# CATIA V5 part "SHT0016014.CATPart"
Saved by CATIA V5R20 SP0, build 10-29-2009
Part number: SHT0016014
Source: Unknown
Bounding box of the stored display mesh (mm): x -544.085 to 25.758, y -866.5 to -591.5, z 0.9 to 106.4
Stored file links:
  C:\Users\hp\Desktop\SHT0016014-宽车主驾驶底部支架焊接总成\SHT0016014.CATPart
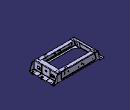
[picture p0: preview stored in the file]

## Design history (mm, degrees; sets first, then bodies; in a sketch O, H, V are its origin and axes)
Body1 "Q37108-焊接方螺母" (main body)
  Solid1: solid without history
Body2 "Q37108-焊接方螺母"
  Solid2: solid without history
Body3 "Q37108-焊接方螺母"
  Solid3: solid without history
Body4 "Q37108-焊接方螺母"
  Solid4: solid without history
Body5 "Q37108-焊接方螺母"
  Solid5: solid without history
Body6 "Q37108-焊接方螺母"
  Solid6: solid without history
Body7 "SHT0016148-宽车主驾驶左侧钣金"
  Solid7: solid without history
Body8 "SHT0016146-宽车主驾驶后侧钣金"
  Solid8: solid without history
Body9 "SHT0016145-宽车主驾驶前侧钣金"
  Solid9: solid without history
Body10 "Q37110-焊接方螺母"
  Solid10: solid without history
Body11 "Q37110-焊接方螺母"
  Solid11: solid without history
Body12 "Q37106-焊接方螺母"
  Solid12: solid without history
Body13 "Q37106-焊接方螺母"
  Solid13: solid without history
Body14 "Q37106-焊接方螺母"
  Solid14: solid without history
Body15 "Q37106-焊接方螺母"
  Solid15: solid without history
Body16 "SHT0016151-支撑轴套"
  Solid16: solid without history
Body17 "SHT0016151-支撑轴套"
  Solid17: solid without history
Body18 "SHT0016151-支撑轴套"
  Solid18: solid without history
Body19 "SHT0016149-宽车主驾驶右侧钣金"
  Solid19: solid without history
Body20 "Q37110-焊接方螺母--M10"
  Sketch1 on face of Solid7, origin (0, -861.5005, 0), H (-1, 0, 0), V (0, 0, 1)
    point P1 (291.1456, 70.9)
    line L1 (299.1456, 78.9) -> (299.1456, 62.9)
    line L2 (299.1456, 62.9) -> (283.1456, 62.9)
    line L3 (283.1456, 62.9) -> (283.1456, 78.9)
    line L4 (283.1456, 78.9) -> (299.1456, 78.9)
    circle A1 centre (291.1456, 70.9) radius 4.5
    reference projected arc E1 centre (291.1456, 70.9) radius 6 from (291.226, 76.8995) to (285.1461, 70.9804) ccw from edge [face of Solid7 | face of Solid7]
    length L4 = 16
    length L3 = 16
    radius A1 = 4.5
    vertical: L1 V, L3 V
    horizontal: L2 H, L4 H
    equidistance: L1 L3 P1, L2 L4 P1
    concentricity: P1 E1
  Pad1: profile Sketch1, direction (0, 1, 0), length 8
  Sketch2 on end face of Pad1, origin (0, -853.5005, 0), H (-1, 0, 0), V (0, 0, 1)
    point P1 (291.1456, 70.9)
    line L1 (291.1456, 85.0421) -> (305.2877, 70.9)
    line L2 (305.2877, 70.9) -> (291.1456, 56.7579)
    line L3 (291.1456, 56.7579) -> (277.0034, 70.9)
    line L4 (277.0034, 70.9) -> (291.1456, 85.0421)
    reference projected circle E1 centre (291.1456, 70.9) radius 4.5 from edge [end face of Pad1 | face of Pad1 from Sketch1.A1]
    construction line L5 (291.1456, 70.9) -> (291.1456, 68.3129)
    angle L5 L4 = 45
    distance L4 L2 = 20
    distance L3 L1 = 20
    equidistance: L1 L3 P1, L2 L4 P1
    concentricity: P1 E1
    perpendicularity: L3 L2, L2 L1, L4 L1
    vertical: L5 V
  Pocket1: profile Sketch2, direction (0, -1, 0), length 6, thin wall 0, second thickness 4
Body21 "Q37110-焊接方螺母--M10"
  Solid20: linked copy from another document
  Set1
    AxisSystem1: origin (-291.1456, -861.5005, 70.9), X (1, 0, 0), Y (0, 1, 0), Z (0, 0, 1)
    AxisSystem2: origin (-141.1456, -861.5005, 70.9), X (1, 0, 0), Y (0, 1, 0), Z (0, 0, 1)
    Plane1 "对称面": type Offset, RefPlane face of Solid7, Offset 132.5, reversed
  AxisToAxis1: ToTransfor Solid20, AxisOrigin AxisSystem1, Axis AxisSystem2
Body22 "Q37110-焊接方螺母--M10"
  Solid21: linked copy from another document
  Symmetry1: ToTransfor Solid21, Reference Plane1
Body23 "Q37110-焊接方螺母--M10"
  Solid22: linked copy from another document
  Symmetry2: ToTransfor Solid22, Reference Plane1
Body24 "Q37106-焊接方螺母--M6"
  Sketch3 on face of Solid7, origin (0, -861.5005, 0), H (-1, 0, 0), V (0, 0, 1)
    point P1 (254.0001, 56.4499)
    line L1 (259.0001, 61.4499) -> (259.0001, 51.4499)
    line L2 (259.0001, 51.4499) -> (249.0001, 51.4499)
    line L3 (249.0001, 51.4499) -> (249.0001, 61.4499)
    line L4 (249.0001, 61.4499) -> (259.0001, 61.4499)
    circle A1 centre (254.0001, 56.4499) radius 2.5
    reference projected arc E1 centre (254.0001, 56.4499) radius 3.5 from (254.0001, 52.9499) to (256.475, 53.975) ccw from edge [face of Solid7 | face of Solid7]
    length L4 = 10
    length L3 = 10
    radius A1 = 2.5
    vertical: L1 V, L3 V
    horizontal: L2 H, L4 H
    equidistance: L1 L3 P1, L2 L4 P1
    concentricity: P1 E1
  Pad2: profile Sketch3, direction (0, 1, 0), length 5
  Sketch4 on end face of Pad2, origin (0, -856.5005, 0), H (-1, 0, 0), V (0, 0, 1)
    point P1 (254.0001, 56.4499)
    line L1 (254.0001, 64.9352) -> (262.4854, 56.4499)
    line L2 (262.4854, 56.4499) -> (254.0001, 47.9646)
    line L3 (254.0001, 47.9646) -> (245.5148, 56.4499)
    line L4 (245.5148, 56.4499) -> (254.0001, 64.9352)
    reference projected circle E1 centre (254.0001, 56.4499) radius 2.5 from edge [end face of Pad2 | face of Pad2 from Sketch3.A1]
    construction line L5 (254.0001, 56.4499) -> (254.0001, 53.8628)
    angle L5 L4 = 45
    distance L4 L2 = 12
    distance L3 L1 = 12
    equidistance: L1 L3 P1, L2 L4 P1
    concentricity: P1 E1
    perpendicularity: L3 L2, L2 L1, L4 L1
    vertical: L5 V
  Pocket2: profile Sketch4, direction (0, -1, 0), length 3.5, thin wall 0, second thickness 4
Body25 "Q37106-焊接方螺母--M6"
  Solid23: linked copy from another document
  Set2
    AxisSystem3: origin (-314.0001, -861.5005, 56.4499), X (1, 0, 0), Y (0, 1, 0), Z (0, 0, 1)
    AxisSystem4: origin (-99.616, -861.5005, 68.166), X (1, 0, 0), Y (0, 1, 0), Z (0, 0, 1)
    AxisSystem5: origin (-99.616, -861.5005, 84.166), X (1, 0, 0), Y (0, 1, 0), Z (0, 0, 1)
    AxisSystem6: origin (-254.0001, -861.5005, 56.4499), X (1, 0, 0), Y (0, 1, 0), Z (0, 0, 1)
  AxisToAxis2: ToTransfor Solid23, AxisOrigin AxisSystem6, Axis AxisSystem3
Body26 "Q37106-焊接方螺母--M6"
  Solid24: linked copy from another document
  AxisToAxis3: ToTransfor Solid24, AxisOrigin AxisSystem6, Axis AxisSystem4
Body27 "Q37106-焊接方螺母--M6"
  Solid25: linked copy from another document
  AxisToAxis4: ToTransfor Solid25, AxisOrigin AxisSystem6, Axis AxisSystem5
